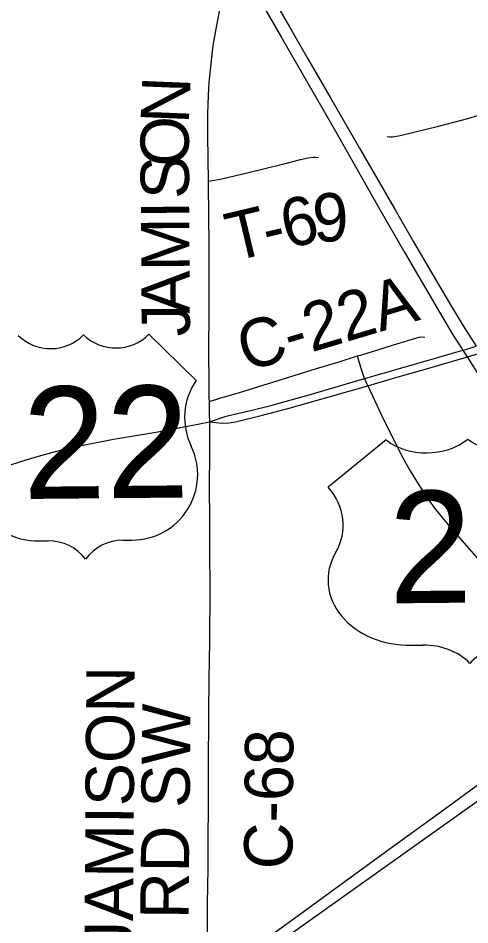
# Model space of a CAD drawing. Extents: x -51392 to 1635000, y 156707 to 696232.
# Drawn here: x 128704 to 131508, y 480308 to 485938 of the extents above; entities that cross this region are included whole.
import ezdxf

# ---------------------------------------------------------------- set-up
doc = ezdxf.new("R2010")
doc.units = 0
for name, color, linetype in [('GM_X_Corporation', 7, 'Continuous'), ('GM_X_County_Road', 7, 'Continuous'), ('GM_X_County_Road_Text', 7, 'Continuous'), ('GM_X_Township_Road', 7, 'Continuous'), ('GM_X_Township_Road_Text', 7, 'Continuous'), ('GM_X_US_Route', 7, 'Continuous'), ('GM_X_US_Shield', 7, 'Continuous')]:
    doc.layers.add(name, color=color, linetype=linetype)

msp = doc.modelspace()

# ---------------------------------------------------------------- linework, layer by layer
at = {"layer": 'GM_X_Corporation'}
msp.add_lwpolyline([(134759.1, 479678.8), (133604.2, 479687.7), (133604.5, 478598.1), (132528.7, 478616.6), (132542.1, 478236.7), (129870.6, 478443.7), (129901.2, 479899.6), (131937.8, 481348.4), (132059.9, 481272.9), (132358.5, 481473.9), (132352.3, 481630), (133028.9, 482100.3), (132919.2, 482222.6), (133794.2, 482822.4), (133776.9, 482846.9), (134696.1, 483492.5)], dxfattribs=at)
at = {"layer": 'GM_X_County_Road'}
for points in [[(129885.9, 484924.9), (129884.5, 485064.8), (129882.1, 485212.2), (129881.6, 485343.4), (129885.3, 485458.2), (129890.3, 485540.1), (129901.2, 485654.5), (129915.3, 485768.5), (129928.5, 485849.5), (129954.9, 485978), (129969.9, 486042), (130005.2, 486168.4), (130029.8, 486246.7), (130053, 486311.9), (130088.4, 486403.8), (130099.2, 486431), (130138.3, 486521.4), (130243.4, 486743.5), (130283, 486833.3), (130299.4, 486875.1)], [(129889.2, 484055.9), (129889.2, 484065.6), (129889.6, 484360.5), (129889.2, 484507.9), (129887.5, 484737.2), (129886.3, 484884.7), (129885.9, 484924.9)], [(129888.5, 483932.7), (129889.2, 484055.9)], [(130811.6, 483840.3), (130837, 483848.3), (131056, 483914.7), (131165.1, 483949), (131196.6, 483957), (131212.8, 483959.4), (131229, 483957.7)], [(129891.3, 483558), (129890.8, 483580.3), (129889.7, 483685.9), (129888.3, 483852.6), (129888.5, 483932.7)], [(129891.3, 483558), (129962.6, 483579.4), (130072.2, 483612.2), (130290.7, 483679.3), (130555.8, 483761.8), (130696.7, 483804.3), (130811.6, 483840.3)], [(130853.5, 483699.9), (130831.8, 483768.4), (130825.1, 483792.4), (130821.8, 483803.9), (130811.6, 483840.3)], [(129894.3, 483430.4), (129892.7, 483481.2), (129891.3, 483558)], [(129882.9, 479962.5), (129877.7, 480016.1), (129876.8, 480081.8), (129879.7, 480442.6), (129882.9, 480655.7), (129883.7, 480819.6), (129884.6, 481065.5), (129886.4, 481278.6), (129888.4, 481622.9), (129890, 481836), (129893.3, 482065.5), (129895, 482393.4), (129894.9, 482639.2), (129894, 482803.1), (129892.8, 483049.1), (129892.9, 483213), (129894.3, 483430.4)]]:
    msp.add_lwpolyline(points, dxfattribs=at)
at = {"layer": 'GM_X_Township_Road'}
for points in [[(130995, 485203.1), (131011.2, 485200), (131027.4, 485200.3), (131043.6, 485201.9), (131075.5, 485208.2), (131313.8, 485266.3), (131503.5, 485316.1), (131550.3, 485330.5), (131581.7, 485339.7), (131598, 485340.6), (131613.2, 485335.6), (131613.3, 485335.6), (131625.2, 485324.7), (131633.7, 485310.8), (131639.7, 485295.5), (131644, 485279.6), (131647.1, 485263.6), (131667.5, 485117.9), (131676.6, 485053.1), (131684.8, 484994.2)], [(129885.9, 484924.9), (129920.2, 484931.3), (129968, 484940.2), (130141.3, 484982), (130346, 485031.5), (130456, 485059.3), (130503.5, 485069.6), (130535.3, 485074.6), (130551.6, 485074.9), (130567.7, 485073.4)]]:
    msp.add_lwpolyline(points, dxfattribs=at)
at = {"layer": 'GM_X_US_Route'}
for points in [[(130035.9, 486341.9), (130053, 486311.9), (130133.3, 486173), (130239.9, 485988.4), (130338.6, 485818.1), (130501.7, 485533.7), (130673.6, 485235.3), (130836, 484950.5), (130940.4, 484764.5), (131105.2, 484481.1), (131319.4, 484112.4), (131403.3, 483971.6), (131425.7, 483936.7)], [(130224.2, 486167.8), (130388.1, 485883.7), (130503.4, 485685.3), (130642.4, 485443.8), (130822.6, 485131.3), (131043.9, 484747.9), (131158.1, 484548.6), (131258, 484379.1), (131382.7, 484167.1), (131467.7, 484026.8), (131547.7, 483900.3)], [(129894.3, 483430.4), (129957.5, 483454.9), (129995.1, 483466.3), (130039.2, 483477.4), (130145.5, 483501.3), (130273, 483533.5), (130510.4, 483599.9), (130853.5, 483699.9), (130877.3, 483706.8), (130920.5, 483719.4), (131315, 483833.8), (131464.2, 483876.4), (131488.7, 483883.3), (131547.7, 483900.3)], [(131425.7, 483936.7), (131464.2, 483876.4), (131479, 483853.2), (131491, 483834.3), (131551.4, 483739.7), (131635.5, 483613.5), (131725.2, 483477.3), (131781.7, 483396.8), (131943.2, 483169.8), (132050.4, 483024.9), (132179.8, 482855.6), (132292.3, 482714.7), (132406.3, 482575), (132543.9, 482412.2), (132697.2, 482240.9), (132745, 482185.2), (132823.9, 482099.2)], [(131466.4, 483827.1), (131491, 483834.3), (131557.5, 483853.7)], [(129894.3, 483430.4), (129970.6, 483422.9), (130012.9, 483425.1), (130053.5, 483431.5), (130213, 483469.8), (130387.4, 483515.8), (130766.1, 483623.3), (130874, 483654.8), (131033.9, 483701.4), (131238.6, 483761.4), (131443.6, 483820.5), (131466.4, 483827.1)], [(130853.5, 483699.9), (130863.7, 483676.2), (130874, 483654.8), (130960.2, 483472.1), (131032.3, 483325), (131092.3, 483208.5), (131131.6, 483136.8), (131182.4, 483052.8), (131236.1, 482970.6), (131283.5, 482904), (131333.5, 482839.4), (131386, 482776.6), (131561, 482578.7), (131602.3, 482533.1), (131933.4, 482166.6), (132142.2, 481935.6), (132295.5, 481764.7), (132322.3, 481734.8)], [(129001.7, 483263.6), (129085.8, 483283), (129295.2, 483323.6), (129570.9, 483369.9), (129700.9, 483393.3), (129894.3, 483430.4)], [(128490.6, 483111.9), (128518.4, 483121), (128752.6, 483195.8), (128831.1, 483218.8), (128974.1, 483257.2), (129001.7, 483263.6)], [(129854.3, 479939.2), (129882.9, 479962.5), (130128.8, 480137.9), (130420.3, 480349.5), (130962.7, 480745.1), (131373, 481043.9), (131544.6, 481170), (131769.9, 481333.4), (132034.5, 481526.4), (132279.6, 481703.8)]]:
    msp.add_lwpolyline(points, dxfattribs=at)
at = {"layer": 'GM_X_US_Shield'}
for p, q in [((129808.5, 483687.3), (129515.7, 483974.6)), ((130987.8, 483319), (130628, 483025.5)), ((128831.7, 482691.9), (128889.7, 482692.4)), ((129353.7, 482696.8), (129411.7, 482697.4)), ((131144.8, 482044.2), (131217.3, 482044.9))]:
    msp.add_line(p, q, dxfattribs=at)
for centre, radius, start, end in [((128904.7, 484176), 290, 226.1115, 314.9656), ((129310.8, 484179.8), 290, 226.1115, 314.9656), ((130143.3, 483457.5), 406.1, 145.5376, 205.9914), ((128823.3, 483097.9), 406.1, 155.3705, 271.1768), ((129412.4, 483103.4), 406.1, 269.9003, 25.7066), ((128892.4, 482402.4), 290, 37.4084, 90.5385), ((129356.4, 482406.8), 290, 90.5385, 143.6686)]:
    msp.add_arc(centre, radius, start, end, dxfattribs=at)
for centre, major_axis, start_param, end_param in [((131239.7, 483528.5), (-362.5, -3.4), 0.795399, 2.346194), ((131747.2, 483533.3), (-362.5, -3.4), 0.795399, 2.346194), ((130214.5, 482788.7), (507.5, 4.8), 5.838949, 6.894067), ((131135.4, 482450.2), (507.5, 4.8), 2.702327, 4.723529), ((131220.1, 481754.9), (-362.5, -3.4), 3.785094, 4.712389), ((131800.1, 481760.3), (-362.5, -3.4), 4.712389, 5.639684)]:
    msp.add_ellipse(centre, major_axis=major_axis, ratio=0.8, start_param=start_param, end_param=end_param, dxfattribs=at)

# ---------------------------------------------------------------- texts
at = {"layer": 'GM_X_County_Road_Text'}
for s, rotation, p in [('N', 87.6339, (129763.2, 485278.7)), ('O', 90.1597, (129764, 485018.2)), ('S', 90.3572, (129765.3, 484816)), ('I', 90.3532, (129766, 484692.8)), ('M', 90.3554, (129768.1, 484367.2)), ('A', 90.3545, (129769.7, 484103.2)), ('C-22A', 16.6358, (130118, 483740.6)), ('J', 90.3541, (129770.6, 483962.4)), ('JAMISON', 89.5917, (129415, 480130.5)), ('RD SW', 89.453, (129761.8, 480343)), ('C-68', 89.5176, (130405.7, 480652.1))]:
    msp.add_text(s, height=300, rotation=rotation, dxfattribs=at).set_placement(p)
at = {"layer": 'GM_X_Township_Road_Text'}
for s, rotation, p in [('6', 13.0967, (130372.9, 484505.6)), ('9', 3.0634, (130539.2, 484545.6)), ('T', 13.3607, (130035, 484425.5)), ('-', 13.329, (130253.3, 484477.3))]:
    msp.add_text(s, height=300, rotation=rotation, dxfattribs=at).set_placement(p)
at = {"layer": 'GM_X_US_Shield'}
for s, p in [('22', (128734, 482952)), ('22I', (131007.1, 482304))]:
    msp.add_text(s, height=696.1, rotation=0.5385, dxfattribs=at).set_placement(p)

doc.saveas('drawing.dxf')
